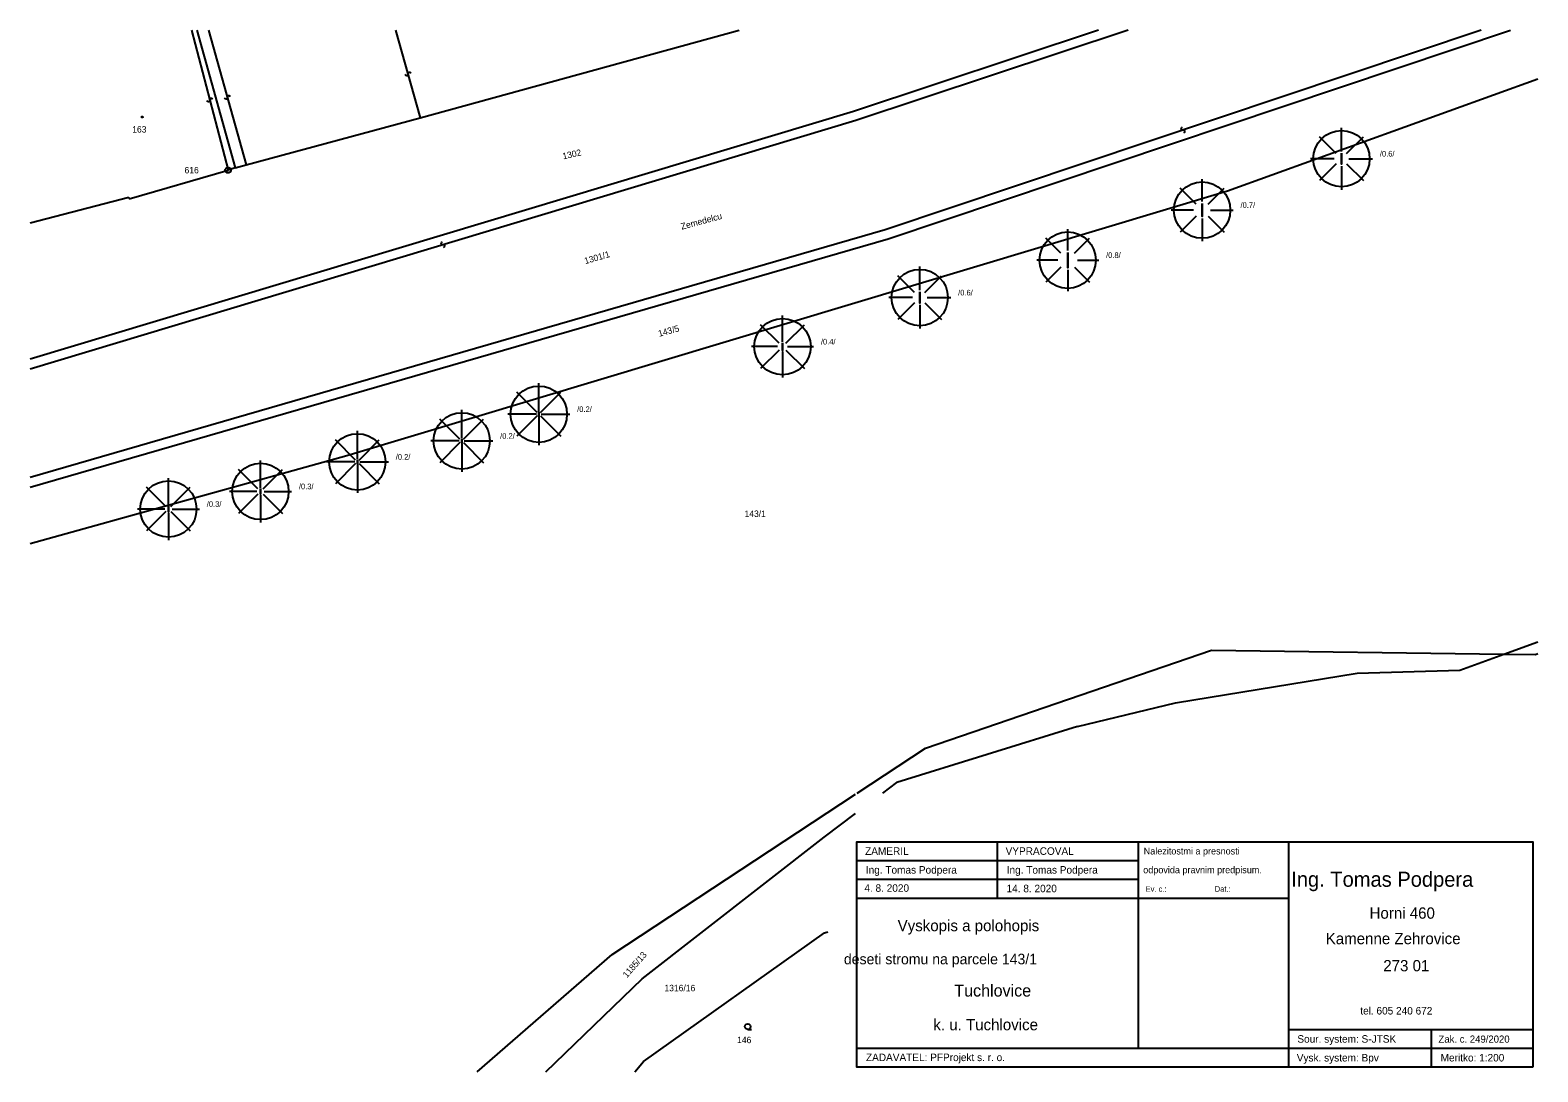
# Model space of a CAD drawing. Extents: x -772681.1 to -772600.9, y -1033083.5 to -1033028.1.
import ezdxf

# ---------------------------------------------------------------- set-up
doc = ezdxf.new("R2010")
doc.units = 0
for name, color, linetype in [('KM_body', 7, 'Continuous'), ('KM_hranice', 7, 'Continuous'), ('KM_kody_budov', 7, 'Continuous'), ('KM_mezni_znaky', 7, 'Continuous'), ('KM_parcelni_cisla', 7, 'Continuous'), ('KM_popis', 7, 'Continuous'), ('KM_vnitrni_kresba', 7, 'Continuous'), ('popisove_pole', 7, 'Continuous'), ('stromy_kere', 7, 'Continuous')]:
    doc.layers.add(name, color=color, linetype=linetype)

msp = doc.modelspace()

# ---------------------------------------------------------------- linework, layer by layer
at = {"layer": 'KM_body'}
msp.add_lwpolyline([(-772642.934, -1033081.256), (-772643.01, -1033081.236), (-772643.064, -1033081.182), (-772643.084, -1033081.108), (-772643.064, -1033081.034), (-772643.01, -1033080.98), (-772642.936, -1033080.96), (-772642.862, -1033080.98), (-772642.808, -1033081.034), (-772642.788, -1033081.11), (-772642.808, -1033081.186), (-772642.862, -1033081.24), (-772642.938, -1033081.26), (-772642.738, -1033081.26)], dxfattribs=at)
at = {"layer": 'KM_hranice'}
for p, q in [((-772672.264, -1033028.066), (-772670.22, -1033035.4)), ((-772660.37, -1033032.74), (-772643.397, -1033028.066)), ((-772624.264, -1033028.066), (-772637.31, -1033032.39)), ((-772635.46, -1033039.17), (-772602.328, -1033028.066)), ((-772600.874, -1033030.684), (-772617.39, -1033036.63)), ((-772637.31, -1033032.39), (-772681.134, -1033045.589)), ((-772669.64, -1033035.23), (-772660.37, -1033032.74)), ((-772670.22, -1033035.4), (-772669.64, -1033035.23)), ((-772675.86, -1033037.05), (-772670.6, -1033035.52)), ((-772670.22, -1033035.4), (-772670.6, -1033035.52)), ((-772617.39, -1033036.63), (-772664.27, -1033050.72)), ((-772681.134, -1033038.329), (-772675.89, -1033036.95)), ((-772675.89, -1033036.95), (-772675.86, -1033037.05)), ((-772681.134, -1033052.399), (-772635.46, -1033039.17)), ((-772664.27, -1033050.72), (-772681.134, -1033055.416)), ((-772602.69, -1033061.28), (-772600.874, -1033060.62)), ((-772633.47, -1033066.29), (-772618.24, -1033061.07)), ((-772618.24, -1033061.07), (-772602.69, -1033061.28)), ((-772605.03, -1033062.13), (-772602.69, -1033061.28)), ((-772602.69, -1033061.28), (-772601, -1033061.3)), ((-772601, -1033061.3), (-772600.874, -1033061.255)), ((-772620.16, -1033063.87), (-772610.49, -1033062.3)), ((-772610.49, -1033062.3), (-772605.03, -1033062.13)), ((-772625.38, -1033065.13), (-772620.16, -1033063.87)), ((-772625.38, -1033065.13), (-772634.99, -1033068.12)), ((-772637.101, -1033068.679), (-772633.47, -1033066.29)), ((-772635.735, -1033068.679), (-772634.99, -1033068.12)), ((-772650.16, -1033077.27), (-772637.19, -1033068.737)), ((-772638.87, -1033071.03), (-772637.19, -1033069.77)), ((-772648.55, -1033078.57), (-772638.87, -1033071.03)), ((-772648.48, -1033082.97), (-772638.85, -1033076.11)), ((-772638.85, -1033076.11), (-772638.677, -1033076.07)), ((-772657.345, -1033083.518), (-772650.16, -1033077.27)), ((-772653.685, -1033083.518), (-772648.55, -1033078.57)), ((-772648.95, -1033083.518), (-772648.48, -1033082.97))]:
    msp.add_line(p, q, dxfattribs=at)
at = {"layer": 'KM_kody_budov'}
msp.add_lwpolyline([(-772675.174, -1033032.656), (-772675.154, -1033032.66), (-772675.144, -1033032.678), (-772675.14, -1033032.69), (-772675.144, -1033032.708), (-772675.16, -1033032.722), (-772675.174, -1033032.724), (-772675.192, -1033032.718), (-772675.204, -1033032.706), (-772675.208, -1033032.69), (-772675.204, -1033032.672), (-772675.188, -1033032.658)], close=True, dxfattribs=at)
at = {"layer": 'KM_mezni_znaky'}
msp.add_line((-772670.61, -1033035.52), (-772670.59, -1033035.52), dxfattribs=at)
msp.add_lwpolyline([(-772670.562, -1033035.376), (-772670.494, -1033035.414), (-772670.456, -1033035.482), (-772670.456, -1033035.56), (-772670.494, -1033035.628), (-772670.562, -1033035.666), (-772670.64, -1033035.666), (-772670.708, -1033035.628), (-772670.746, -1033035.56), (-772670.746, -1033035.482), (-772670.708, -1033035.414), (-772670.64, -1033035.376)], close=True, dxfattribs=at)
at = {"layer": 'KM_vnitrni_kresba'}
for p, q in [((-772672.554, -1033028.066), (-772670.6, -1033035.52)), ((-772671.637, -1033028.066), (-772669.64, -1033035.23)), ((-772661.68, -1033028.066), (-772660.37, -1033032.74)), ((-772622.678, -1033028.066), (-772637.18, -1033032.87)), ((-772603.899, -1033028.066), (-772635.62, -1033038.7)), ((-772637.18, -1033032.87), (-772681.134, -1033046.108)), ((-772635.62, -1033038.7), (-772681.134, -1033051.882))]:
    msp.add_line(p, q, dxfattribs=at)
for points in [[(-772660.878, -1033030.372), (-772660.913, -1033030.32), (-772660.979, -1033030.313), (-772661.024, -1033030.355), (-772661.031, -1033030.457), (-772661.078, -1033030.495), (-772661.142, -1033030.484), (-772661.172, -1033030.434)], [(-772671.429, -1033031.765), (-772671.464, -1033031.712), (-772671.53, -1033031.704), (-772671.575, -1033031.745), (-772671.584, -1033031.847), (-772671.632, -1033031.884), (-772671.695, -1033031.872), (-772671.725, -1033031.821)], [(-772670.491, -1033031.617), (-772670.527, -1033031.565), (-772670.593, -1033031.559), (-772670.637, -1033031.6), (-772670.644, -1033031.702), (-772670.692, -1033031.74), (-772670.755, -1033031.728), (-772670.786, -1033031.679)], [(-772619.721, -1033033.528), (-772619.671, -1033033.49), (-772619.668, -1033033.424), (-772619.712, -1033033.382), (-772619.813, -1033033.38), (-772619.854, -1033033.335), (-772619.846, -1033033.271), (-772619.798, -1033033.238)], [(-772659.124, -1033039.636), (-772659.072, -1033039.599), (-772659.067, -1033039.533), (-772659.109, -1033039.489), (-772659.211, -1033039.484), (-772659.25, -1033039.438), (-772659.24, -1033039.374), (-772659.191, -1033039.343)]]:
    msp.add_lwpolyline(points, dxfattribs=at)
at = {"layer": 'popisove_pole'}
for p, q in [((-772629.632, -1033074.266), (-772629.632, -1033071.266)), ((-772622.132, -1033082.266), (-772622.132, -1033071.266)), ((-772614.132, -1033083.266), (-772614.132, -1033071.266)), ((-772637.132, -1033072.266), (-772622.132, -1033072.266)), ((-772637.132, -1033073.266), (-772622.132, -1033073.266)), ((-772637.132, -1033074.266), (-772614.132, -1033074.266)), ((-772614.132, -1033081.266), (-772601.132, -1033081.266)), ((-772606.532, -1033083.266), (-772606.532, -1033081.266)), ((-772637.132, -1033082.266), (-772601.132, -1033082.266))]:
    msp.add_line(p, q, dxfattribs=at)
msp.add_lwpolyline([(-772601.132, -1033083.266), (-772637.132, -1033083.266), (-772637.132, -1033071.266), (-772601.132, -1033071.266)], close=True, dxfattribs=at)
at = {"layer": 'stromy_kere'}
for p, q in [((-772611.328, -1033034.518), (-772611.328, -1033033.258)), ((-772611.604, -1033034.633), (-772612.494, -1033033.742)), ((-772611.052, -1033034.633), (-772610.161, -1033033.742)), ((-772611.718, -1033034.908), (-772612.978, -1033034.908)), ((-772611.604, -1033035.184), (-772612.494, -1033036.075)), ((-772611.052, -1033035.184), (-772610.161, -1033036.075)), ((-772610.938, -1033034.908), (-772609.678, -1033034.908)), ((-772618.747, -1033037.189), (-772618.747, -1033035.994)), ((-772611.328, -1033035.298), (-772611.328, -1033036.558)), ((-772619.069, -1033037.322), (-772619.914, -1033036.477)), ((-772618.426, -1033037.322), (-772617.581, -1033036.477)), ((-772619.202, -1033037.644), (-772620.397, -1033037.644)), ((-772618.292, -1033037.644), (-772617.097, -1033037.644)), ((-772619.069, -1033037.966), (-772619.914, -1033038.811)), ((-772618.747, -1033038.099), (-772618.747, -1033039.294)), ((-772618.426, -1033037.966), (-772617.581, -1033038.811)), ((-772626.271, -1033039.943), (-772627.07, -1033039.144)), ((-772625.903, -1033039.79), (-772625.903, -1033038.66)), ((-772625.535, -1033039.943), (-772624.736, -1033039.144)), ((-772633.78, -1033041.913), (-772633.78, -1033040.653)), ((-772626.423, -1033040.31), (-772627.553, -1033040.31)), ((-772626.271, -1033040.678), (-772627.07, -1033041.477)), ((-772625.903, -1033040.83), (-772625.903, -1033041.96)), ((-772625.535, -1033040.678), (-772624.736, -1033041.477)), ((-772625.383, -1033040.31), (-772624.253, -1033040.31)), ((-772634.055, -1033042.027), (-772634.946, -1033041.136)), ((-772633.504, -1033042.027), (-772632.613, -1033041.136)), ((-772634.17, -1033042.303), (-772635.43, -1033042.303)), ((-772633.39, -1033042.303), (-772632.13, -1033042.303)), ((-772641.084, -1033044.654), (-772641.084, -1033043.264)), ((-772634.055, -1033042.579), (-772634.946, -1033043.469)), ((-772633.78, -1033042.693), (-772633.78, -1033043.953)), ((-772633.504, -1033042.579), (-772632.613, -1033043.469)), ((-772641.268, -1033044.73), (-772642.251, -1033043.747)), ((-772640.9, -1033044.73), (-772639.917, -1033043.747)), ((-772641.344, -1033044.914), (-772642.734, -1033044.914)), ((-772641.268, -1033045.098), (-772642.251, -1033046.08)), ((-772641.084, -1033045.174), (-772641.084, -1033046.564)), ((-772640.9, -1033045.098), (-772639.917, -1033046.08)), ((-772640.824, -1033044.914), (-772639.434, -1033044.914)), ((-772654.058, -1033048.38), (-772654.058, -1033046.86)), ((-772654.15, -1033048.418), (-772655.225, -1033047.343)), ((-772653.967, -1033048.418), (-772652.892, -1033047.343)), ((-772658.253, -1033049.842), (-772659.328, -1033048.767)), ((-772658.161, -1033049.803), (-772658.161, -1033048.283)), ((-772658.069, -1033049.842), (-772656.994, -1033048.767)), ((-772654.188, -1033048.51), (-772655.708, -1033048.51)), ((-772654.15, -1033048.602), (-772655.225, -1033049.677)), ((-772654.058, -1033048.64), (-772654.058, -1033050.16)), ((-772653.967, -1033048.602), (-772652.892, -1033049.677)), ((-772653.928, -1033048.51), (-772652.408, -1033048.51)), ((-772663.716, -1033050.918), (-772663.716, -1033049.398)), ((-772663.808, -1033050.956), (-772664.883, -1033049.881)), ((-772663.624, -1033050.956), (-772662.549, -1033049.881)), ((-772658.291, -1033049.933), (-772659.811, -1033049.933)), ((-772658.253, -1033050.025), (-772659.328, -1033051.1)), ((-772658.161, -1033050.063), (-772658.161, -1033051.583)), ((-772658.069, -1033050.025), (-772656.994, -1033051.1)), ((-772658.031, -1033049.933), (-772656.511, -1033049.933)), ((-772668.873, -1033052.425), (-772668.873, -1033050.97)), ((-772663.846, -1033051.048), (-772665.366, -1033051.048)), ((-772663.808, -1033051.14), (-772664.883, -1033052.214)), ((-772663.716, -1033051.178), (-772663.716, -1033052.698)), ((-772663.624, -1033051.14), (-772662.549, -1033052.214)), ((-772663.586, -1033051.048), (-772662.066, -1033051.048)), ((-772673.776, -1033053.363), (-772673.776, -1033051.908)), ((-772669.011, -1033052.482), (-772670.04, -1033051.453)), ((-772668.735, -1033052.482), (-772667.706, -1033051.453)), ((-772673.914, -1033053.42), (-772674.942, -1033052.391)), ((-772673.638, -1033053.42), (-772672.609, -1033052.391)), ((-772669.068, -1033052.62), (-772670.523, -1033052.62)), ((-772669.011, -1033052.758), (-772670.04, -1033053.787)), ((-772668.873, -1033052.815), (-772668.873, -1033054.27)), ((-772668.735, -1033052.758), (-772667.706, -1033053.787)), ((-772668.678, -1033052.62), (-772667.223, -1033052.62)), ((-772673.971, -1033053.558), (-772675.426, -1033053.558)), ((-772673.914, -1033053.696), (-772674.942, -1033054.725)), ((-772673.638, -1033053.696), (-772672.609, -1033054.725)), ((-772673.581, -1033053.558), (-772672.126, -1033053.558)), ((-772673.776, -1033053.753), (-772673.776, -1033055.208))]:
    msp.add_line(p, q, dxfattribs=at)
for points in [[(-772611.328, -1033034.608), (-772611.328, -1033035.208), (-772611.328, -1033034.608)], [(-772618.747, -1033037.294), (-772618.747, -1033037.994), (-772618.747, -1033037.294)], [(-772625.903, -1033039.91), (-772625.903, -1033040.71), (-772625.903, -1033039.91)], [(-772633.78, -1033042.003), (-772633.78, -1033042.603), (-772633.78, -1033042.003)], [(-772641.084, -1033044.714), (-772641.084, -1033045.114), (-772641.084, -1033044.714)], [(-772654.058, -1033048.41), (-772654.058, -1033048.61), (-772654.058, -1033048.41)], [(-772658.161, -1033049.833), (-772658.161, -1033050.033), (-772658.161, -1033049.833)], [(-772663.716, -1033050.948), (-772663.716, -1033051.148), (-772663.716, -1033050.948)], [(-772668.873, -1033052.47), (-772668.873, -1033052.77), (-772668.873, -1033052.47)], [(-772673.776, -1033053.408), (-772673.776, -1033053.708), (-772673.776, -1033053.408)]]:
    msp.add_lwpolyline(points, dxfattribs=at)
for centre in [(-772611.328, -1033034.908), (-772618.747, -1033037.644), (-772625.903, -1033040.31), (-772633.78, -1033042.303), (-772641.084, -1033044.914), (-772654.058, -1033048.51), (-772658.161, -1033049.933), (-772663.716, -1033051.048), (-772668.873, -1033052.62), (-772673.776, -1033053.558)]:
    msp.add_circle(centre, 1.5, dxfattribs=at)

# ---------------------------------------------------------------- texts
at = {"layer": 'KM_mezni_znaky'}
msp.add_text('616', height=0.34, dxfattribs=at).set_placement((-772672.916, -1033035.69))
at = {"layer": 'KM_parcelni_cisla'}
for s, p in [('163', (-772675.701, -1033033.517)), ('143/1', (-772643.106, -1033053.977)), ('146', (-772643.502, -1033081.991))]:
    msp.add_text(s, height=0.34, dxfattribs=at).set_placement(p)
for s, rotation, p in [('1302', 12.37589, (-772652.755, -1033034.947)), ('1301/1', 16.15741, (-772651.579, -1033040.525)), ('143/5', 15.41256, (-772647.649, -1033044.392)), ('1185/13', 48.70141, (-772649.367, -1033078.54))]:
    msp.add_text(s, height=0.34, rotation=rotation, dxfattribs=at).set_placement(p)
at = {"layer": 'KM_popis'}
msp.add_text('Zemedelcu', height=0.34, rotation=15.12609, dxfattribs=at).set_placement((-772646.444, -1033038.692))
msp.add_text('1316/16', height=0.34, dxfattribs=at).set_placement((-772647.371, -1033079.226))
at = {"layer": 'popisove_pole'}
for s, height, p in [('ZAMERIL', 0.4, (-772636.686, -1033071.966)), ('VYPRACOVAL', 0.4, (-772629.207, -1033071.966)), ('Nalezitostmi a presnosti', 0.36, (-772621.856, -1033071.946)), ('Ing. Tomas Podpera', 0.4, (-772636.648, -1033072.966)), ('Ing. Tomas Podpera', 0.4, (-772629.148, -1033072.966)), ('odpovida pravnim predpisum.', 0.36, (-772621.881, -1033072.946)), ('Ing. Tomas Podpera', 0.8, (-772614.003, -1033073.666)), ('4. 8. 2020', 0.4, (-772636.726, -1033073.935)), ('14. 8. 2020', 0.4, (-772629.156, -1033073.958)), ('Ev. c.: ', 0.3, (-772621.755, -1033073.935)), ('Dat.: ', 0.3, (-772618.075, -1033073.93)), ('Vyskopis a polohopis ', 0.6, (-772634.955, -1033076.031)), ('Horni 460', 0.6, (-772609.833, -1033075.366)), ('Kamenne Zehrovice', 0.6, (-772612.167, -1033076.722)), ('deseti stromu na parcele 143/1', 0.56, (-772637.816, -1033077.794)), ('273 01', 0.6, (-772609.103, -1033078.166)), ('Tuchlovice', 0.64, (-772631.938, -1033079.51)), (' tel. 605 240 672', 0.4, (-772610.474, -1033080.466)), ('k. u. Tuchlovice', 0.6, (-772633.056, -1033081.305)), ('Sour. system: S-JTSK', 0.4, (-772613.676, -1033081.966)), ('Zak. c. 249/2020', 0.38, (-772606.162, -1033081.964)), ('ZADAVATEL: PFProjekt s. r. o.', 0.4, (-772636.64, -1033082.947)), ('Vysk. system: Bpv', 0.4, (-772613.707, -1033082.966)), ('Meritko: 1:200', 0.4, (-772606.048, -1033082.966))]:
    msp.add_text(s, height=height, dxfattribs=at).set_placement(p)
at = {"layer": 'stromy_kere'}
for s, p in [('/0.6/', (-772609.284, -1033034.794)), ('/0.7/', (-772616.704, -1033037.529)), ('/0.8/', (-772623.859, -1033040.196)), ('/0.6/', (-772631.736, -1033042.188)), ('/0.4/', (-772639.04, -1033044.799)), ('/0.2/', (-772652.015, -1033048.395)), ('/0.2/', (-772656.117, -1033049.819)), ('/0.2/', (-772661.672, -1033050.933)), ('/0.3/', (-772666.829, -1033052.505)), ('/0.3/', (-772671.732, -1033053.443))]:
    msp.add_text(s, height=0.3, dxfattribs=at).set_placement(p)

doc.saveas('drawing.dxf')
